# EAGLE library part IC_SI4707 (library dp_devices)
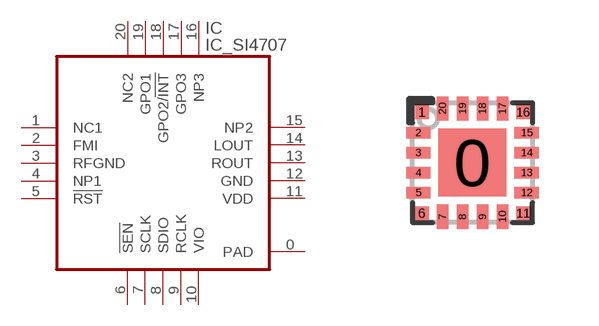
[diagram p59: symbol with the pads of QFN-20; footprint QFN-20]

Designator prefix IC

## IC_SI4707  [QFN-20]
0  PAD
1  NC1
2  FMI
3  RFGND
4  NP1
5  !RST
6  !SEN
7  SCLK
8  SDIO
9  RCLK
10  VIO
11  VDD
12  GND
13  ROUT
14  LOUT
15  NP2
16  NP3
17  GPO3
18  GPO2/!INT
19  GPO1
20  NC2

## Footprint QFN-20 (pad centres in mm)
smd 1.7 x 1.7: 0 0,0
smd 0.34 x 0.34: 1 -1.265,1.265; 6 -1.265,-1.265; 11 1.265,-1.265; 16 1.265,1.265
smd 0.61 x 0.28: 2 -1.355,0.75; 3 -1.355,0.25; 4 -1.355,-0.25; 5 -1.355,-0.75; 12 1.355,-0.75; 13 1.355,-0.25; 14 1.355,0.25; 15 1.355,0.75
smd 0.28 x 0.61: 7 -0.75,-1.355; 8 -0.25,-1.355; 9 0.25,-1.355; 10 0.75,-1.355; 17 0.75,1.355; 18 0.25,1.355; 19 -0.25,1.355; 20 -0.75,1.355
